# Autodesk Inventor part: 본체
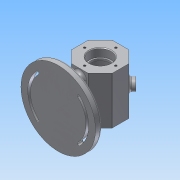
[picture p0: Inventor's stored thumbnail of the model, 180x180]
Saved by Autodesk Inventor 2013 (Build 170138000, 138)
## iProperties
Created: 2017-06
Part Number: 본체
Material: 알루미늄 6061
Document SubType Name: Modeling
Designer: Administrator
Density: 2.71 g/cm^3
Mass: 562.565 g
Surface Area: 565.689 cm^2
Volume: 207.589 cm^3
Author: Administrator
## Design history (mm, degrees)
node "작업 평면1"
sketch "스케치2"
  geometry: C1 r 55 at (0, 0); 1 further point
  constraints: 1 centre point, 1 coincident
  dimensions: "d4" = 110 diameter of C1
extrude "돌출2" join sketch "스케치2" distance "d5" = 10; taper "d6" = 0 deg
sketch "스케치3"
  geometry: L1 (-24, 29)-(-52, 29); L2 (-52, 29)-(-52, -29); L3 (-52, -29)-(-24, -29); L4 (-24, -29)-(-24, 29); L5 (-52, -55)-(-52, 55) reference; 1 further point
  constraints: 8 end point, 2 parallel, 1 collinear, 1 horizontal, 1 perpendicular
  dimensions: "d8" = 58 distance of L1.end L2.end; "d10" = 29 distance from line of point (0, 0) L1; "d11" = 24 distance from line of point (0, 0) L4
extrude "돌출3" join sketch "스케치3" stored distance "d12" = 10; taper "d13" = 0 deg
sketch "스케치5"
  geometry: L1 (-12.426, 30)-(12.426, 30); L2 (12.426, 30)-(30, 12.426); L3 (30, 12.426)-(30, -12.426); L4 (30, -12.426)-(12.426, -30); L5 (12.426, -30)-(-12.426, -30); L6 (-12.426, -30)-(-30, -12.426); L7 (-30, -12.426)-(-30, 12.426); L8 (-30, 12.426)-(-12.426, 30); 2 further points
  constraints: 16 end point, 1 coincident, 1 horizontal, 17 other
  dimensions: "d18" = 60 distance between parallel lines of L5 L1
extrude "돌출5" join sketch "스케치5" stored distance "d19" = 70; taper "d20" = 0 deg
sketch "스케치6"
  geometry: C1 r 8 at (-12.426, 35); 1 further point
  constraints: 1 centre point, 1 coincident
  dimensions: "d21" = 16 diameter of C1
extrude "돌출6" join sketch "스케치6" distance "d22" = 7; taper "d23" = 0 deg
sketch "스케치7"
  geometry: L1 (0, 0)-(-43, 43); L2 (0, 0)-(60.811, 0); L3 (0, 0)-(-44.214, -44.214); C1 r 55 at (0, 0) reference; A1 r 48 centre (0, 0) between (-33.941, 33.941) and (-33.941, -33.941); A2 r 5 centre (-30.406, 30.406) between (-26.87, 26.87) and (-33.941, 33.941); A3 r 5 centre (-30.406, -30.406) between (-33.941, -33.941) and (-26.87, -26.87); A4 r 38 centre (0, 0) between (-26.87, 26.87) and (-26.87, -26.87); A5 r 2 centre (-30.406, -30.406) between (-31.82, -31.82) and (-28.991, -28.991); A6 r 2 centre (-30.406, 30.406) between (-28.991, 28.991) and (-31.82, 31.82); A7 r 45 centre (0, 0) between (-31.82, 31.82) and (-31.82, -31.82); A8 r 41 centre (0, 0) between (-28.991, 28.991) and (-28.991, -28.991)
  constraints: 16 point on circle, 8 centre point, 7 coincident, 6 end point, 4 point on line, 1 equal length, 1 horizontal
  dimensions: "d24" = 96 diameter of A1; "d26" = 135 deg angle of L2 L1; "d27" = 90 deg angle of L1 L3; "d28" = 76 diameter of A4; "d29" = 10 diameter of A3; "d30" = 10 diameter of A2; "d31" = 4 diameter of A5; "d32" = 4 diameter of A6; "d33" = 82 diameter of A8; "d34" = 90 diameter of A7
extrude "돌출7" cut sketch "스케치7" distance "d35" = 3; taper "d36" = 0 deg
extrude "돌출8" cut sketch "스케치7" stored distance "d37" = 3; taper "d38" = 0 deg
sketch "스케치8"
  geometry: 2 further points
  constraints: 1 coincident
hole "구멍1" sketch "스케치8" at (0, 0) diameter "d39" = 28; stored, may be unused: countersink angle "d43" = 90 deg, drill point angle "d45" = 0 deg; dims "d40" = 6, "d41" = 32, "d42" = 12, "d44" = 8
sketch "스케치9"
  geometry: L1 (25, 20)-(0, 20); L2 (0, 20)-(0, -20); L3 (0, -20)-(25, -20); L4 (25, -20)-(25, 20); 2 further points
  constraints: 8 end point, 2 parallel, 1 coincident, 1 horizontal, 1 midpoint, 1 perpendicular
  dimensions: "d46" = 40 distance of L3.end L1.start; "d48" = 25 distance of L2.end L3.end
revolve "회전1" sketch "스케치9" stored, may be unused: angle "d49" = 90 deg
hole "구멍2" diameter "d52" = 28; stored, may be unused: countersink angle "d56" = 90 deg, drill point angle "d58" = 0 deg; dims "d50" = 10, "d51" = 10, "d53" = 6, "d54" = 32, "d55" = 12, "d57" = 8
chamfer "모따기1" distance "d59" = 1; stored, may be unused: second distance "d60" = 2, angle "d61" = 45 deg
fillet "모깎기1" dims "d62" = 0.3
sketch "스케치10"
  geometry: C1 r 17 at (0, 0) reference; 1 further point
  constraints: 1 vertical alignment
  dimensions: "d63" = 23 distance of C1.centre point (0, 23)
hole "구멍3" sketch "스케치10" at (0, 23) diameter "d64" = 3.242; stored, may be unused: countersink angle "d68" = 90 deg, drill point angle "d70" = 118 deg; dims "d65" = 8, "d66" = 32, "d67" = 12, "d69" = 10
hole "구멍4" diameter "d76" = 8; stored, may be unused: countersink angle "d80" = 90 deg, drill point angle "d82" = 118 deg; dims "d74" = 10, "d75" = 10, "d77" = 8, "d78" = 32, "d79" = 12, "d81" = 15
fillet "모깎기2" dims "d83" = 3
sketch "스케치11"
  geometry: L1 (0, 0)-(-17.574, 0) reference; L2 (-17.574, 0)-(-17.574, 70) reference; 2 further points
  constraints: 1 other
  dimensions: "d84" = 35 distance from line of L1 point (12.426, 35); "d85" = 30 distance from line of point (12.426, 35) L2
feature "엠보싱1" sketch "스케치11" dims "d5" = 10, "d18" = 60, "d86" = 0.5, "d87" = 0
fillet "모깎기3" dims "d88" = 5
fillet "모깎기4" dims "d89" = 5
fillet "모깎기5" dims "d90" = 3
fillet "모깎기6" dims "d91" = 1
fillet "모깎기7" dims "d92" = 3
node "솔리드1"
mirror "대칭1"
pattern_circular "원형 패턴1" dims angle "d72" = 360 deg
mirror "대칭2"
other parameters: "d3" = -62, "d25" = 86
